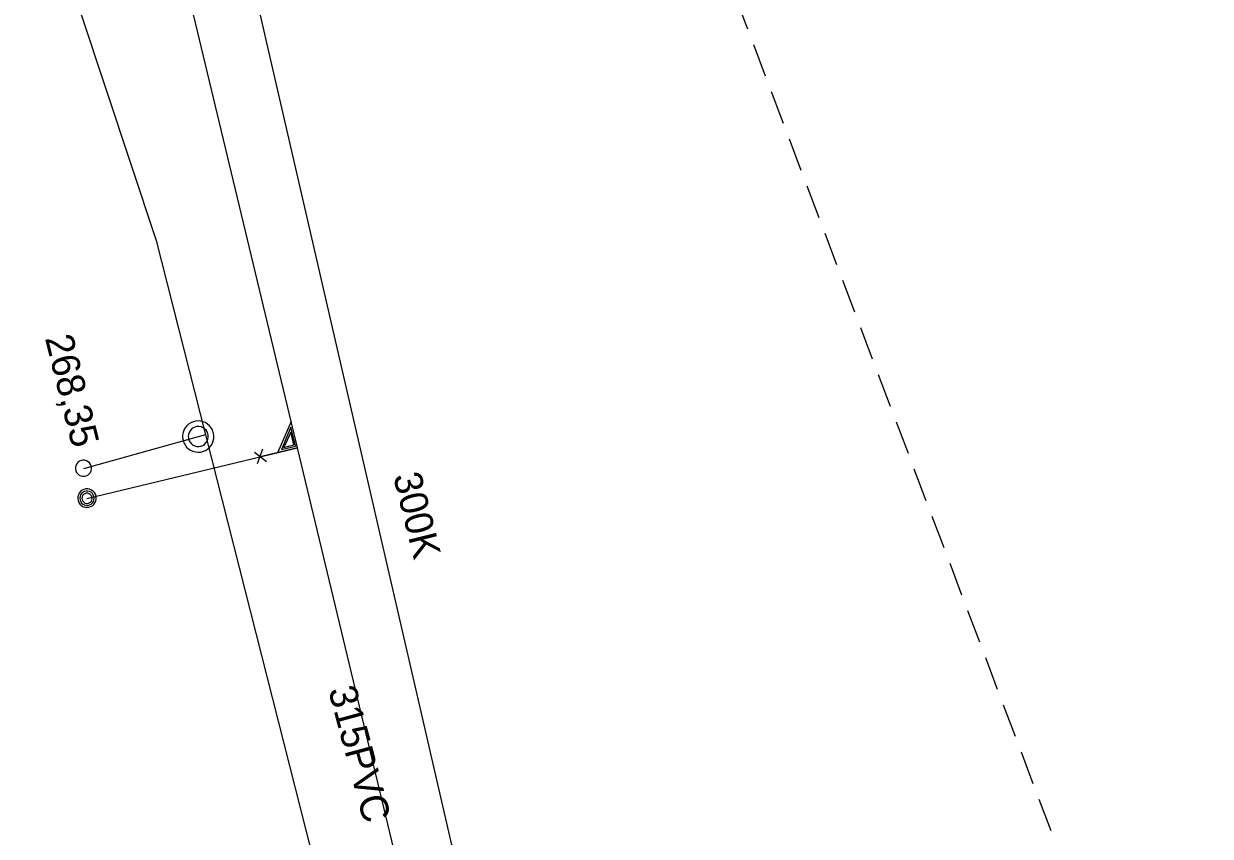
# Model space of a CAD drawing. Extents: x -732074 to -731966, y -1048695 to -1047982.
# Drawn here: x -732000.3 to -731966.41, y -1048598 to -1048574.8 of the extents above; entities that cross this region are included whole.
import ezdxf

# ---------------------------------------------------------------- set-up
doc = ezdxf.new("R2010")
doc.units = 0
doc.header["$LTSCALE"] = 0.32
doc.linetypes.add('MEDIUM_DASHED', pattern=[4.5, 3, -1.5])
doc.layers.add('1', color=7, linetype='Continuous')
for name, color, linetype, lineweight in [('18', 7, 'Continuous', 13), ('20', 7, 'Continuous', 13), ('49', 7, 'Continuous', 13), ('63', 7, 'MEDIUM_DASHED', 25), ('8', 7, 'Continuous', 13)]:
    doc.layers.add(name, color=color, linetype=linetype, lineweight=lineweight)

msp = doc.modelspace()

# ---------------------------------------------------------------- linework, layer by layer
at = {"layer": '18'}
for p, q in [((-731993.706, -1048587.034), (-731993.366, -1048587.297)), ((-731993.614, -1048587.36), (-731993.464, -1048586.943))]:
    msp.add_line(p, q, dxfattribs=at)
for points in [[(-731993.543, -1048587.16), (-731992.477, -1048586.904), (-731992.657, -1048586.155), (-731993.039, -1048587.039)], [(-731992.866, -1048586.897), (-731992.583, -1048586.829), (-731992.669, -1048586.468), (-731992.865, -1048586.899)]]:
    msp.add_lwpolyline(points, dxfattribs=at)
for points in [[(-731992.937, -1048586.962), (-731992.532, -1048586.865), (-731992.664, -1048586.316)], [(-731998.225, -1048588.347), (-731998.23, -1048588.291), (-731998.247, -1048588.238), (-731998.276, -1048588.189), (-731998.315, -1048588.148), (-731998.36, -1048588.116), (-731998.413, -1048588.094), (-731998.468, -1048588.083), (-731998.524, -1048588.085), (-731998.578, -1048588.098), (-731998.629, -1048588.123), (-731998.674, -1048588.158), (-731998.71, -1048588.201), (-731998.735, -1048588.251), (-731998.75, -1048588.306), (-731998.752, -1048588.362), (-731998.744, -1048588.417), (-731998.723, -1048588.47), (-731998.691, -1048588.516), (-731998.651, -1048588.555), (-731998.603, -1048588.585), (-731998.551, -1048588.604), (-731998.495, -1048588.611), (-731998.438, -1048588.607), (-731998.384, -1048588.59), (-731998.335, -1048588.563), (-731998.294, -1048588.525), (-731998.261, -1048588.48), (-731998.237, -1048588.429), (-731998.225, -1048588.374)], [(-731998.284, -1048588.35), (-731998.289, -1048588.301), (-731998.308, -1048588.255), (-731998.335, -1048588.214), (-731998.372, -1048588.181), (-731998.416, -1048588.159), (-731998.465, -1048588.147), (-731998.514, -1048588.147), (-731998.561, -1048588.159), (-731998.605, -1048588.182), (-731998.642, -1048588.215), (-731998.671, -1048588.256), (-731998.688, -1048588.303), (-731998.693, -1048588.352), (-731998.686, -1048588.401), (-731998.669, -1048588.447), (-731998.641, -1048588.487), (-731998.603, -1048588.52), (-731998.559, -1048588.542), (-731998.511, -1048588.554), (-731998.462, -1048588.553), (-731998.414, -1048588.541), (-731998.37, -1048588.517), (-731998.333, -1048588.484), (-731998.306, -1048588.443), (-731998.289, -1048588.396)], [(-731998.343, -1048588.354), (-731998.348, -1048588.312), (-731998.365, -1048588.274), (-731998.394, -1048588.243), (-731998.428, -1048588.22), (-731998.468, -1048588.209), (-731998.511, -1048588.209), (-731998.551, -1048588.221), (-731998.585, -1048588.244), (-731998.612, -1048588.276), (-731998.629, -1048588.314), (-731998.634, -1048588.355), (-731998.629, -1048588.397), (-731998.61, -1048588.434), (-731998.583, -1048588.466), (-731998.546, -1048588.488), (-731998.507, -1048588.499), (-731998.465, -1048588.498), (-731998.424, -1048588.485), (-731998.391, -1048588.462), (-731998.364, -1048588.429), (-731998.348, -1048588.391)]]:
    msp.add_lwpolyline(points, close=True, dxfattribs=at)
at = {"layer": '20'}
for points in [[(-731987.18, -1048608.96), (-731988.807, -1048602.179), (-731992.473, -1048586.913), (-731996.42, -1048570.48)], [(-731987.18, -1048608.96), (-731988.807, -1048602.179), (-731992.473, -1048586.913), (-731996.42, -1048570.48)], [(-731984.98, -1048611.47), (-731986.302, -1048605.878), (-731994.199, -1048571.66)], [(-731984.98, -1048611.47), (-731986.302, -1048605.878), (-731994.199, -1048571.66)]]:
    msp.add_lwpolyline(points, dxfattribs=at)
at = {"layer": '49'}
msp.add_line((-731998.489, -1048588.36), (-731992.473, -1048586.913), dxfattribs=at)
msp.add_line((-731998.489, -1048588.36), (-731992.473, -1048586.913), dxfattribs=at)
at = {"layer": '63'}
msp.add_lwpolyline([(-732020.748, -1048466.307), (-731967.071, -1048608.112), (-731967.071, -1048608.113), (-731967.071, -1048608.115), (-731966.405, -1048694.807)], dxfattribs=at)
at = {"layer": '8'}
for p, q in [((-731995.102, -1048586.543), (-731995.309, -1048586.6)), ((-731995.309, -1048586.6), (-731998.588, -1048587.506))]:
    msp.add_line(p, q, dxfattribs=at)
at = {"layer": '8', "lineweight": 25}
msp.add_lwpolyline([(-732007.629, -1048549.38), (-732002.27, -1048563.66), (-731996.51, -1048580.99), (-731995.102, -1048586.543), (-731992.07, -1048598.5), (-731991.625, -1048601.24), (-731990.239, -1048608.37)], dxfattribs=at)
at = {"layer": '8'}
for points in [[(-731994.88, -1048586.47), (-731994.905, -1048586.401), (-731994.941, -1048586.338), (-731994.987, -1048586.281), (-731995.042, -1048586.232), (-731995.104, -1048586.192), (-731995.17, -1048586.164), (-731995.241, -1048586.147), (-731995.315, -1048586.141), (-731995.387, -1048586.148), (-731995.459, -1048586.166), (-731995.526, -1048586.196), (-731995.587, -1048586.237), (-731995.64, -1048586.285), (-731995.685, -1048586.344), (-731995.72, -1048586.408), (-731995.744, -1048586.477), (-731995.756, -1048586.55), (-731995.757, -1048586.622), (-731995.746, -1048586.695), (-731995.722, -1048586.764), (-731995.688, -1048586.829), (-731995.644, -1048586.887), (-731995.591, -1048586.938), (-731995.53, -1048586.978), (-731995.464, -1048587.009), (-731995.393, -1048587.028), (-731995.32, -1048587.036), (-731995.247, -1048587.031), (-731995.176, -1048587.015), (-731995.108, -1048586.987), (-731995.046, -1048586.948), (-731994.991, -1048586.9), (-731994.944, -1048586.843), (-731994.907, -1048586.78), (-731994.882, -1048586.711), (-731994.867, -1048586.64), (-731994.865, -1048586.567), (-731994.875, -1048586.495)], [(-731995.035, -1048586.513), (-731995.057, -1048586.458), (-731995.089, -1048586.409), (-731995.129, -1048586.367), (-731995.178, -1048586.335), (-731995.232, -1048586.313), (-731995.29, -1048586.303), (-731995.349, -1048586.304), (-731995.406, -1048586.318), (-731995.458, -1048586.343), (-731995.506, -1048586.378), (-731995.545, -1048586.422), (-731995.573, -1048586.472), (-731995.591, -1048586.528), (-731995.598, -1048586.587), (-731995.592, -1048586.645), (-731995.575, -1048586.701), (-731995.546, -1048586.752), (-731995.508, -1048586.797), (-731995.461, -1048586.832), (-731995.409, -1048586.858), (-731995.352, -1048586.871), (-731995.293, -1048586.874), (-731995.236, -1048586.864), (-731995.181, -1048586.843), (-731995.132, -1048586.812), (-731995.09, -1048586.77), (-731995.058, -1048586.721), (-731995.037, -1048586.668), (-731995.026, -1048586.61), (-731995.028, -1048586.551)], [(-731998.368, -1048587.433), (-731998.387, -1048587.384), (-731998.418, -1048587.341), (-731998.457, -1048587.306), (-731998.503, -1048587.28), (-731998.554, -1048587.266), (-731998.606, -1048587.264), (-731998.658, -1048587.273), (-731998.706, -1048587.294), (-731998.748, -1048587.325), (-731998.782, -1048587.366), (-731998.806, -1048587.413), (-731998.819, -1048587.463), (-731998.82, -1048587.516), (-731998.809, -1048587.567), (-731998.787, -1048587.615), (-731998.754, -1048587.656), (-731998.714, -1048587.689), (-731998.666, -1048587.712), (-731998.615, -1048587.723), (-731998.562, -1048587.723), (-731998.512, -1048587.711), (-731998.464, -1048587.688), (-731998.424, -1048587.654), (-731998.392, -1048587.612), (-731998.371, -1048587.564), (-731998.36, -1048587.513), (-731998.362, -1048587.46)]]:
    msp.add_lwpolyline(points, close=True, dxfattribs=at)

# ---------------------------------------------------------------- texts
at = {"layer": '1'}
for s, rotation, p in [('268,35', 284, (-731999.692, -1048583.777)), ('300K', 284, (-731989.749, -1048587.714)), ('315PVC', 285, (-731991.602, -1048593.822))]:
    msp.add_text(s, height=0.8, rotation=rotation, dxfattribs=at).set_placement(p)

doc.saveas('drawing.dxf')
